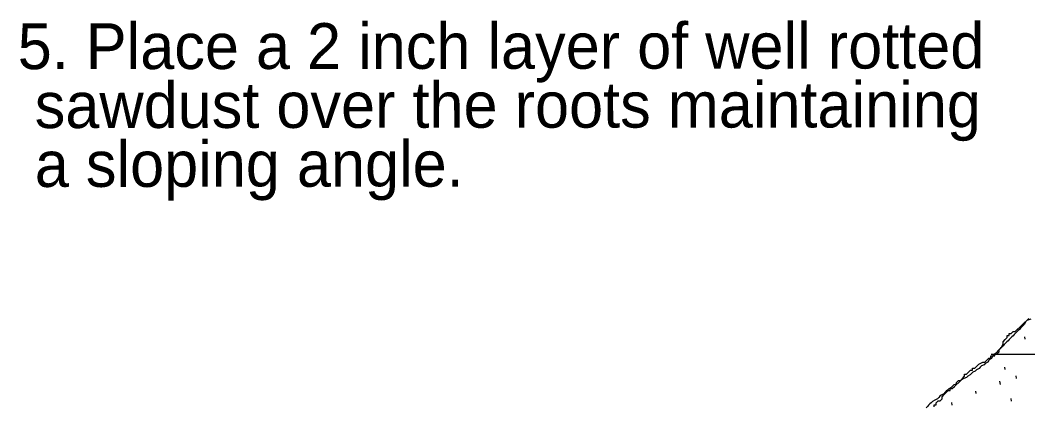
# Model space of a CAD drawing. Extents: x 1728110 to 1729925, y 1284214 to 1285339.
# Drawn here: x 1728278.3 to 1728429.9, y 1284486.8 to 1284545 of the extents above; entities that cross this region are included whole.
import ezdxf

# ---------------------------------------------------------------- set-up
doc = ezdxf.new("R2010")
doc.units = 0
doc.layers.add('Reforestation Detail CELL', color=7, linetype='Continuous')

msp = doc.modelspace()

# ---------------------------------------------------------------- linework, layer by layer
at = {"layer": 'Reforestation Detail CELL'}
for p, q in [((1728429.44, 1284497.37), (1728429.48, 1284496.99)), ((1728424.39, 1284494.74), (1728547.57, 1284494.83)), ((1728426.4, 1284492.81), (1728426.45, 1284492.43)), ((1728425.68, 1284490.7), (1728425.74, 1284490.19)), ((1728428.11, 1284491.48), (1728428.16, 1284491.1)), ((1728422.04, 1284489.2), (1728422.09, 1284488.82)), ((1728418.44, 1284487.49), (1728418.48, 1284487.1)), ((1728427.36, 1284488.06), (1728427.4, 1284487.68))]:
    msp.add_line(p, q, dxfattribs=at)
for points in [[(1728430.36, 1284500), (1728429.79, 1284499.81), (1728429.6, 1284499.62), (1728429.41, 1284499.24), (1728429.22, 1284499.05), (1728429.03, 1284498.86), (1728428.84, 1284498.67), (1728428.65, 1284498.48), (1728428.46, 1284498.29), (1728428.27, 1284498.1), (1728428.08, 1284497.91), (1728427.89, 1284497.72), (1728427.7, 1284497.53), (1728427.51, 1284497.34), (1728427.32, 1284497.15), (1728427.14, 1284496.96), (1728426.95, 1284496.77), (1728426.76, 1284496.58), (1728426.57, 1284496.39), (1728426.38, 1284496.2), (1728426.19, 1284496.01), (1728426, 1284495.82), (1728425.81, 1284495.63), (1728425.43, 1284495.25), (1728425.24, 1284495.06), (1728425.05, 1284494.87), (1728424.86, 1284494.68), (1728424.67, 1284494.49), (1728424.48, 1284494.11), (1728424.1, 1284493.92), (1728423.91, 1284493.54), (1728423.53, 1284493.35), (1728423.34, 1284493.16), (1728422.96, 1284492.97), (1728422.77, 1284492.78), (1728422.58, 1284492.59), (1728422.21, 1284492.4), (1728422.02, 1284492.21), (1728421.64, 1284492.02), (1728421.45, 1284491.83), (1728421.26, 1284491.64), (1728420.88, 1284491.45), (1728420.69, 1284491.26), (1728420.31, 1284491.07), (1728419.93, 1284490.88), (1728419.74, 1284490.69), (1728419.55, 1284490.5), (1728419.36, 1284490.31), (1728418.79, 1284490.12), (1728418.41, 1284489.73), (1728418.03, 1284489.55), (1728417.84, 1284489.35), (1728417.65, 1284489.17), (1728417.46, 1284488.98), (1728417.28, 1284488.79), (1728416.89, 1284488.59), (1728416.71, 1284488.41), (1728416.52, 1284488.21), (1728416.33, 1284488.02), (1728415.95, 1284487.83), (1728415.57, 1284487.64), (1728415.38, 1284487.45), (1728415.19, 1284487.27), (1728415, 1284487.08), (1728414.81, 1284486.88), (1728414.62, 1284486.7)], [(1728415.81, 1284486.82), (1728415.81, 1284487.13), (1728416.12, 1284487.13), (1728416.12, 1284487.43), (1728416.42, 1284487.74), (1728416.73, 1284487.74), (1728417.03, 1284488.05), (1728417.03, 1284488.35), (1728417.34, 1284488.66), (1728417.65, 1284488.97), (1728417.95, 1284489.27), (1728418.26, 1284489.27), (1728418.26, 1284489.58), (1728418.56, 1284489.58), (1728418.87, 1284489.89), (1728419.17, 1284490.19), (1728419.17, 1284490.5), (1728419.48, 1284490.8), (1728419.78, 1284490.8), (1728420.09, 1284491.11), (1728420.4, 1284491.42), (1728420.4, 1284491.72), (1728420.7, 1284491.72), (1728421.01, 1284492.03), (1728421.31, 1284492.34), (1728421.62, 1284492.34), (1728421.62, 1284492.64), (1728421.93, 1284492.64), (1728422.23, 1284492.95), (1728422.54, 1284493.25), (1728423.15, 1284493.56), (1728423.45, 1284493.56), (1728423.76, 1284493.87), (1728424.06, 1284494.17), (1728424.37, 1284494.17), (1728424.37, 1284494.48), (1728424.68, 1284494.48), (1728424.98, 1284494.48), (1728424.98, 1284494.79), (1728425.29, 1284494.79), (1728425.59, 1284495.09), (1728425.59, 1284495.4), (1728425.9, 1284495.71), (1728426.2, 1284496.32), (1728426.2, 1284496.62), (1728426.51, 1284496.93), (1728426.82, 1284497.24), (1728426.82, 1284497.54), (1728427.12, 1284497.54), (1728427.12, 1284497.85), (1728427.43, 1284497.85), (1728427.73, 1284498.16), (1728428.04, 1284498.16), (1728430.09, 1284500.11)]]:
    msp.add_lwpolyline(points, dxfattribs=at)

# ---------------------------------------------------------------- texts
for s, p in [('5. Place a 2 inch layer of well rotted ', (1728277.94, 1284537.6)), (' sawdust over the roots maintaining ', (1728277.94, 1284528.74)), (' a sloping angle.', (1728277.95, 1284519.89))]:
    msp.add_text(s, height=6.8898, rotation=0.0429, dxfattribs=at).set_placement(p)

doc.saveas('drawing.dxf')
